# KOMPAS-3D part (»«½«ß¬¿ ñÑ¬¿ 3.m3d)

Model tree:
1. Эскиз:1
2. Операция выдавливания:1
     Толщина стенки 1 = 2.3; Толщина стенки 2 = 2.3; Расстояние 1 = 0.6; Расстояние 2 = 0.6
3. Эскиз:2
4. Операция выдавливания:2
     Толщина стенки 1 = 2.3; Толщина стенки 2 = 2.3; Расстояние 1 = 0.6; Расстояние 2 = 0.6
5. Эскиз:3
6. Вырезать элемент выдавливания:1
     Толщина стенки 1 = 3; Толщина стенки 2 = 3; Расстояние 1 = 10
7. Эскиз:4
8. Вырезать элемент выдавливания:2
     Толщина стенки 1 = 3; Толщина стенки 2 = 3; Расстояние 1 = 10
9. Вырезать элемент выдавливания:3
     Расстояние 1 = 10
